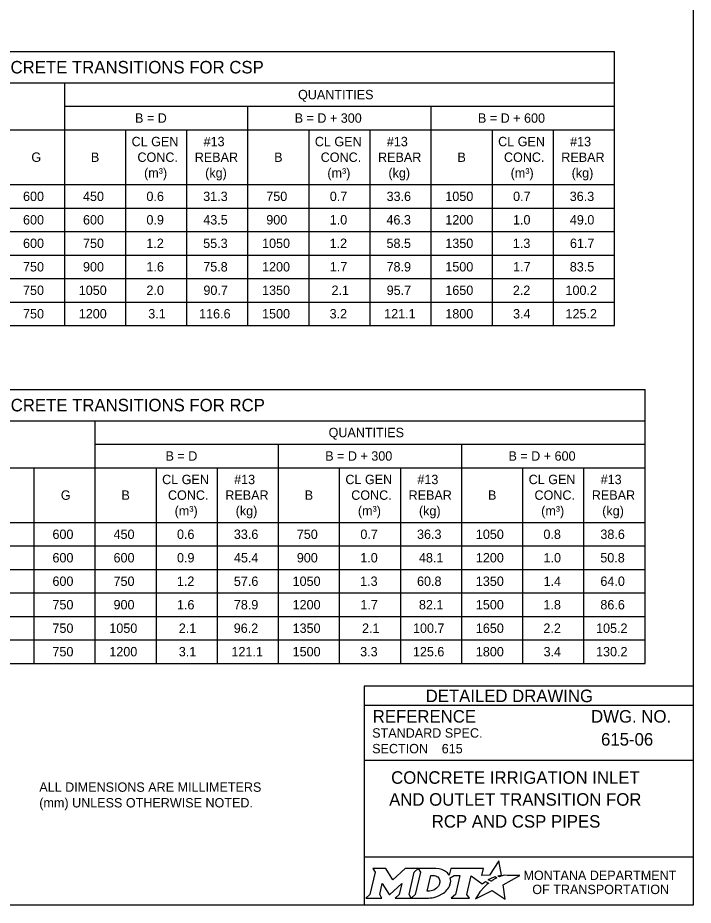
# Model space of a CAD drawing. Extents: x 49991.4 to 50043, y 49987.6 to 50011.4.
# Drawn here: x 50012.44 to 50016.75, y 49987.8 to 49993.47 of the extents above; entities that cross this region are included whole.
import ezdxf

# ---------------------------------------------------------------- set-up
doc = ezdxf.new("R2010")
doc.units = 0
for name, color, linetype in [('Default', 7, 'Continuous'), ('Level 1', 7, 'Continuous'), ('Level 2', 7, 'Continuous'), ('Level 5', 7, 'Continuous')]:
    doc.layers.add(name, color=color, linetype=linetype)

msp = doc.modelspace()

# ---------------------------------------------------------------- linework, layer by layer
at = {"layer": 'Default'}
for points in [[(50015.5126, 49987.9811), (50015.5023, 49987.9867), (50015.5139, 49987.9895), (50015.5255, 49987.9915), (50015.5081, 49988.0816), (50015.4486, 49987.9903), (50015.4013, 49987.9896), (50015.4116, 49988.0337), (50015.2024, 49988.0338), (50015.1923, 49987.9913), (50015.1865, 49987.9996)], [(50014.7056, 49988.0338), (50014.7197, 49988.0104), (50014.6862, 49987.8671), (50014.6605, 49987.8446), (50014.7621, 49987.8446), (50014.7486, 49987.8674), (50014.7648, 49987.9375), (50014.8085, 49987.8685), (50014.8138, 49987.8685), (50014.8889, 49987.938), (50014.8725, 49987.8669), (50014.8478, 49987.8449), (50014.9494, 49987.8449), (50014.9356, 49987.8682), (50014.9688, 49988.0106)], [(50014.9688, 49988.0106), (50014.9941, 49988.0338), (50014.9117, 49988.0338), (50014.8321, 49987.9608), (50014.7876, 49988.0335), (50014.7056, 49988.0338)], [(50015.1077, 49988.0338), (50014.9941, 49988.0338), (50015.0088, 49988.0109), (50014.9749, 49987.8671), (50014.9494, 49987.8449), (50015.06, 49987.8449)], [(50015.1317, 49987.9471), (50015.1305, 49987.939), (50015.1273, 49987.9297), (50015.1231, 49987.9215), (50015.1175, 49987.914), (50015.111, 49987.9071), (50015.1031, 49987.9008), (50015.0948, 49987.8961), (50015.0857, 49987.8922), (50015.0766, 49987.8899), (50015.0674, 49987.889), (50015.0515, 49987.889), (50015.0751, 49987.989), (50015.0911, 49987.989), (50015.0987, 49987.9884), (50015.1063, 49987.9865), (50015.1129, 49987.9835), (50015.119, 49987.9793), (50015.1238, 49987.9743), (50015.1275, 49987.9683), (50015.1302, 49987.9621), (50015.1318, 49987.9547), (50015.1318, 49987.9517), (50015.1317, 49987.9471)], [(50015.3882, 49987.8843), (50015.3729, 49987.8599), (50015.3682, 49987.8524), (50015.3624, 49987.8438), (50015.3601, 49987.8395), (50015.4654, 49987.8926), (50015.5493, 49987.8375), (50015.5362, 49987.9302), (50015.6431, 49987.9886), (50015.5938, 49987.9894), (50015.5637, 49987.9898), (50015.5429, 49987.9901), (50015.5361, 49987.9886), (50015.5312, 49987.9874), (50015.5228, 49987.9851), (50015.5126, 49987.9811)], [(50015.1991, 49987.9747), (50015.2237, 49987.9878), (50015.2606, 49987.9878), (50015.232, 49987.8673), (50015.2045, 49987.8446), (50015.3207, 49987.8446), (50015.3037, 49987.8675), (50015.3319, 49987.9877), (50015.4032, 49987.936), (50015.4243, 49987.9511), (50015.444, 49987.9402)], [(50015.4622, 49987.9535), (50015.4598, 49987.9518), (50015.4415, 49987.9614), (50015.4518, 49987.9671), (50015.4559, 49987.9693), (50015.4645, 49987.9733), (50015.4702, 49987.9759), (50015.4781, 49987.9789), (50015.4854, 49987.9816), (50015.4972, 49987.9742), (50015.4932, 49987.9721), (50015.4886, 49987.9696), (50015.4844, 49987.9674), (50015.4794, 49987.9645), (50015.4775, 49987.9634), (50015.4748, 49987.9618), (50015.4723, 49987.9604), (50015.47, 49987.9588), (50015.4674, 49987.957), (50015.4647, 49987.9552), (50015.4622, 49987.9535)], [(50015.4021, 49987.9004), (50015.4021, 49987.9004)], [(50015.1057, 49987.8522), (50015.1141, 49987.8548), (50015.1271, 49987.8602), (50015.1475, 49987.8712)]]:
    msp.add_lwpolyline(points, dxfattribs=at)
for centre, radius, start, end in [((50015.1308, 49987.9554), 0.0709, 339.5329, 15.8582), ((50015.0868, 49987.9727), 0.1183, 300.9103, 339.1383)]:
    msp.add_arc(centre, radius, start, end, dxfattribs=at)
for centre, major_axis, ratio, start_param, end_param in [((50015.1056, 49987.9864), (0.0834, -0.0037), 0.568097, 0.61298, 1.570796), ((50015.1612, 49987.9937), (0.0361, -0.0295), 0.469099, 1.225588, 1.570796), ((50015.4329, 49987.9305), (-0.0112, -0.0097), 0.021651, 3.157348, 6.283185), ((50015.3952, 49987.8923), (-0.00694, -0.00806), 0.008222, 0, 3.137361), ((50015.4119, 49987.9106), (-0.0098, -0.0102), 0.016458, 3.141593, 6.279097), ((50015.0603, 49987.9932), (0, 0.1484), 0.987302, 3.139398, 3.456847)]:
    msp.add_ellipse(centre, major_axis=major_axis, ratio=ratio, start_param=start_param, end_param=end_param, dxfattribs=at)
at = {"layer": 'Level 1'}
msp.add_lwpolyline([(49999.3835, 49998.9992), (50016.7501, 49998.9992), (50016.7501, 49987.7988), (49999.3835, 49987.7988)], close=True, dxfattribs=at)
at = {"layer": 'Level 2'}
for p, q in [((50008.8375, 49993.2523), (50016.2475, 49993.2523)), ((50008.8375, 49993.0523), (50016.2475, 49993.0523)), ((50012.7375, 49992.9023), (50016.2475, 49992.9023)), ((50008.8375, 49992.7523), (50016.2475, 49992.7523)), ((50008.8375, 49992.4023), (50016.2475, 49992.4023)), ((50008.8375, 49992.2523), (50016.2475, 49992.2523)), ((50008.8375, 49992.1023), (50016.2475, 49992.1023)), ((50008.8375, 49991.9523), (50016.2475, 49991.9523)), ((50008.8375, 49991.8023), (50016.2475, 49991.8023)), ((50008.8375, 49991.6523), (50016.2475, 49991.6523)), ((50008.8375, 49991.5023), (50016.2475, 49991.5023))]:
    msp.add_line(p, q, dxfattribs=at)
for points in [[(50016.2475, 49991.5023), (50016.2475, 49993.2523)], [(50012.7375, 49991.5023), (50012.7375, 49993.0523)], [(50013.9075, 49991.5023), (50013.9075, 49992.9023)], [(50015.0775, 49991.5023), (50015.0775, 49992.9023)], [(50013.1275, 49991.5023), (50013.1275, 49992.7523)], [(50013.5175, 49991.5023), (50013.5175, 49992.7523)], [(50014.2975, 49991.5023), (50014.2975, 49992.7523)], [(50014.6875, 49991.5023), (50014.6875, 49992.7523)], [(50015.4675, 49991.5023), (50015.4675, 49992.7523)], [(50015.8575, 49991.5023), (50015.8575, 49992.7523)], [(50008.6425, 49991.0937), (50016.4425, 49991.0937)], [(50016.4425, 49989.3437), (50016.4425, 49991.0937)], [(50008.6425, 49990.8937), (50016.4425, 49990.8937)], [(50012.9325, 49989.3437), (50012.9325, 49990.8937)], [(50012.9325, 49990.7437), (50016.4425, 49990.7437)], [(50014.1025, 49989.3437), (50014.1025, 49990.7437)], [(50015.2725, 49989.3437), (50015.2725, 49990.7437)], [(50008.6425, 49990.5937), (50016.4425, 49990.5937)], [(50012.5425, 49989.3437), (50012.5425, 49990.5937)], [(50013.3225, 49989.3437), (50013.3225, 49990.5937)], [(50013.7125, 49989.3437), (50013.7125, 49990.5937)], [(50014.4925, 49989.3437), (50014.4925, 49990.5937)], [(50014.8825, 49989.3437), (50014.8825, 49990.5937)], [(50015.6625, 49989.3437), (50015.6625, 49990.5937)], [(50016.0525, 49989.3437), (50016.0525, 49990.5937)], [(50008.6425, 49990.2437), (50016.4425, 49990.2437)], [(50008.6425, 49990.0937), (50016.4425, 49990.0937)], [(50008.6425, 49989.9437), (50016.4425, 49989.9437)], [(50008.6425, 49989.7937), (50016.4425, 49989.7937)], [(50008.6425, 49989.6437), (50016.4425, 49989.6437)], [(50008.6425, 49989.4937), (50016.4425, 49989.4937)], [(50008.6425, 49989.3437), (50016.4425, 49989.3437)]]:
    msp.add_lwpolyline(points, dxfattribs=at)
at = {"layer": 'Level 5'}
for p, q in [((50016.7501, 49989.1988), (50014.6501, 49989.1988)), ((50014.6501, 49989.1988), (50014.6501, 49987.7988)), ((50016.7501, 49989.0738), (50014.6501, 49989.0738)), ((50016.3862, 49988.8587), (50016.3862, 49988.8587)), ((50015.1444, 49988.7993), (50015.1444, 49988.7993)), ((50016.7501, 49988.7238), (50014.6501, 49988.7238)), ((50015.7001, 49988.4747), (50015.7001, 49988.4747)), ((50016.7501, 49988.1057), (50014.6501, 49988.1057))]:
    msp.add_line(p, q, dxfattribs=at)

# ---------------------------------------------------------------- texts
at = {"layer": 'Default'}
for s, p in [('MONTANA DEPARTMENT', (50015.6663, 49987.96)), ('OF TRANSPORTATION', (50015.7225, 49987.87))]:
    msp.add_text(s, height=0.06, dxfattribs=at).set_placement(p)
at = {"layer": 'Level 2'}
for s, height, p in [('METRIC INLET AND OUTLET CONCRETE TRANSITIONS FOR CSP', 0.08, (50010.6738, 49993.1123)), ('QUANTITIES', 0.06, (50014.2272, 49992.9473)), ('B = D', 0.06, (50013.1863, 49992.7973)), ('B = D + 300', 0.06, (50014.2056, 49992.7973)), ('B = D + 600', 0.06, (50015.3756, 49992.7973)), ('CL GEN', 0.06, (50013.1644, 49992.6473)), ('#13', 0.06, (50013.6241, 49992.6473)), ('CL GEN', 0.06, (50014.3344, 49992.6473)), ('#13', 0.06, (50014.7941, 49992.6473)), ('CL GEN', 0.06, (50015.5044, 49992.6473)), ('#13', 0.06, (50015.9641, 49992.6473)), ('G', 0.06, (50012.5248, 49992.5473)), ('B', 0.06, (50012.9048, 49992.5473)), ('CONC.', 0.06, (50013.2017, 49992.5473)), ('REBAR', 0.06, (50013.5677, 49992.5473)), ('B', 0.06, (50014.0748, 49992.5473)), ('CONC.', 0.06, (50014.3717, 49992.5473)), ('REBAR', 0.06, (50014.7377, 49992.5473)), ('B', 0.06, (50015.2448, 49992.5473)), ('CONC.', 0.06, (50015.5417, 49992.5473)), ('REBAR', 0.06, (50015.9077, 49992.5473)), ('(m³)', 0.06, (50013.2443, 49992.4473)), ('(kg)', 0.06, (50013.6341, 49992.4473)), ('(m³)', 0.06, (50014.4143, 49992.4473)), ('(kg)', 0.06, (50014.8041, 49992.4473)), ('(m³)', 0.06, (50015.5843, 49992.4473)), ('(kg)', 0.06, (50015.9741, 49992.4473)), ('600', 0.06, (50012.4714, 49992.2973)), ('450', 0.06, (50012.8543, 49992.2973)), ('0.6', 0.06, (50013.2593, 49992.2973)), ('31.3', 0.06, (50013.6216, 49992.2973)), ('750', 0.06, (50014.0243, 49992.2973)), ('0.7', 0.06, (50014.43, 49992.2973)), ('33.6', 0.06, (50014.7923, 49992.2973)), ('1050', 0.06, (50015.1674, 49992.2973)), ('0.7', 0.06, (50015.6, 49992.2973)), ('36.3', 0.06, (50015.9616, 49992.2973)), ('600', 0.06, (50012.4714, 49992.1473)), ('600', 0.06, (50012.8543, 49992.1473)), ('0.9', 0.06, (50013.2593, 49992.1473)), ('43.5', 0.06, (50013.6219, 49992.1473)), ('900', 0.06, (50014.0243, 49992.1473)), ('1.0', 0.06, (50014.4294, 49992.1473)), ('46.3', 0.06, (50014.7916, 49992.1473)), ('1200', 0.06, (50015.1674, 49992.1473)), ('1.0', 0.06, (50015.5994, 49992.1473)), ('49.0', 0.06, (50015.9625, 49992.1473)), ('600', 0.06, (50012.4714, 49991.9973)), ('750', 0.06, (50012.8543, 49991.9973)), ('1.2', 0.06, (50013.2586, 49991.9973)), ('55.3', 0.06, (50013.6216, 49991.9973)), ('1050', 0.06, (50013.9974, 49991.9973)), ('1.2', 0.06, (50014.4286, 49991.9973)), ('58.5', 0.06, (50014.7919, 49991.9973)), ('1350', 0.06, (50015.1674, 49991.9973)), ('1.3', 0.06, (50015.5986, 49991.9973)), ('61.7', 0.06, (50015.963, 49991.9973)), ('750', 0.06, (50012.4714, 49991.8473)), ('900', 0.06, (50012.8543, 49991.8473)), ('1.6', 0.06, (50013.2593, 49991.8473)), ('75.8', 0.06, (50013.6218, 49991.8473)), ('1200', 0.06, (50013.9974, 49991.8473)), ('1.7', 0.06, (50014.43, 49991.8473)), ('78.9', 0.06, (50014.7923, 49991.8473)), ('1500', 0.06, (50015.1674, 49991.8473)), ('1.7', 0.06, (50015.6, 49991.8473)), ('83.5', 0.06, (50015.9619, 49991.8473)), ('750', 0.06, (50012.4714, 49991.6973)), ('1050', 0.06, (50012.8274, 49991.6973)), ('2.0', 0.06, (50013.2594, 49991.6973)), ('90.7', 0.06, (50013.623, 49991.6973)), ('1350', 0.06, (50013.9974, 49991.6973)), ('2.1', 0.06, (50014.4408, 49991.6973)), ('95.7', 0.06, (50014.793, 49991.6973)), ('1650', 0.06, (50015.1674, 49991.6973)), ('2.2', 0.06, (50015.5986, 49991.6973)), ('100.2', 0.06, (50015.9347, 49991.6973)), ('750', 0.06, (50012.4714, 49991.5473)), ('1200', 0.06, (50012.8274, 49991.5473)), ('3.1', 0.06, (50013.2708, 49991.5473)), ('116.6', 0.06, (50013.5954, 49991.5473)), ('1500', 0.06, (50013.9974, 49991.5473)), ('3.2', 0.06, (50014.4286, 49991.5473)), ('121.1', 0.06, (50014.7769, 49991.5473)), ('1800', 0.06, (50015.1674, 49991.5473)), ('3.4', 0.06, (50015.5998, 49991.5473)), ('125.2', 0.06, (50015.9347, 49991.5473)), ('METRIC INLET AND OUTLET CONCRETE TRANSITIONS FOR RCP', 0.08, (50010.6749, 49990.9537)), ('QUANTITIES', 0.06, (50014.4222, 49990.7887)), ('B = D', 0.06, (50013.3813, 49990.6387)), ('B = D + 300', 0.06, (50014.4006, 49990.6387)), ('B = D + 600', 0.06, (50015.5706, 49990.6387)), ('CL GEN', 0.06, (50013.3594, 49990.4887)), ('#13', 0.06, (50013.8191, 49990.4887)), ('CL GEN', 0.06, (50014.5294, 49990.4887)), ('#13', 0.06, (50014.9891, 49990.4887)), ('CL GEN', 0.06, (50015.6994, 49990.4887)), ('#13', 0.06, (50016.1591, 49990.4887)), ('G', 0.06, (50012.7127, 49990.3887)), ('B', 0.06, (50013.0998, 49990.3887)), ('CONC.', 0.06, (50013.3967, 49990.3887)), ('REBAR', 0.06, (50013.7627, 49990.3887)), ('B', 0.06, (50014.2698, 49990.3887)), ('CONC.', 0.06, (50014.5667, 49990.3887)), ('REBAR', 0.06, (50014.9327, 49990.3887)), ('B', 0.06, (50015.4398, 49990.3887)), ('CONC.', 0.06, (50015.7367, 49990.3887)), ('REBAR', 0.06, (50016.1027, 49990.3887)), ('(m³)', 0.06, (50013.4393, 49990.2887)), ('(kg)', 0.06, (50013.8291, 49990.2887)), ('(m³)', 0.06, (50014.6093, 49990.2887)), ('(kg)', 0.06, (50014.9991, 49990.2887)), ('(m³)', 0.06, (50015.7793, 49990.2887)), ('(kg)', 0.06, (50016.1691, 49990.2887)), ('600', 0.06, (50012.6593, 49990.1387)), ('450', 0.06, (50013.0493, 49990.1387)), ('0.6', 0.06, (50013.4543, 49990.1387)), ('33.6', 0.06, (50013.8173, 49990.1387)), ('750', 0.06, (50014.2193, 49990.1387)), ('0.7', 0.06, (50014.625, 49990.1387)), ('36.3', 0.06, (50014.9866, 49990.1387)), ('1050', 0.06, (50015.3624, 49990.1387)), ('0.8', 0.06, (50015.7938, 49990.1387)), ('38.6', 0.06, (50016.1573, 49990.1387)), ('600', 0.06, (50012.6593, 49989.9887)), ('600', 0.06, (50013.0493, 49989.9887)), ('0.9', 0.06, (50013.4543, 49989.9887)), ('45.4', 0.06, (50013.8178, 49989.9887)), ('900', 0.06, (50014.2193, 49989.9887)), ('1.0', 0.06, (50014.6244, 49989.9887)), ('48.1', 0.06, (50014.9989, 49989.9887)), ('1200', 0.06, (50015.3624, 49989.9887)), ('1.0', 0.06, (50015.7944, 49989.9887)), ('50.8', 0.06, (50016.1568, 49989.9887)), ('600', 0.06, (50012.6593, 49989.8387)), ('750', 0.06, (50013.0493, 49989.8387)), ('1.2', 0.06, (50013.4536, 49989.8387)), ('57.6', 0.06, (50013.8173, 49989.8387)), ('1050', 0.06, (50014.1924, 49989.8387)), ('1.3', 0.06, (50014.6236, 49989.8387)), ('60.8', 0.06, (50014.9868, 49989.8387)), ('1350', 0.06, (50015.3624, 49989.8387)), ('1.4', 0.06, (50015.7948, 49989.8387)), ('64.0', 0.06, (50016.1575, 49989.8387)), ('750', 0.06, (50012.6593, 49989.6887)), ('900', 0.06, (50013.0493, 49989.6887)), ('1.6', 0.06, (50013.4543, 49989.6887)), ('78.9', 0.06, (50013.8173, 49989.6887)), ('1200', 0.06, (50014.1924, 49989.6887)), ('1.7', 0.06, (50014.625, 49989.6887)), ('82.1', 0.06, (50014.9989, 49989.6887)), ('1500', 0.06, (50015.3624, 49989.6887)), ('1.8', 0.06, (50015.7938, 49989.6887)), ('86.6', 0.06, (50016.1573, 49989.6887)), ('750', 0.06, (50012.6593, 49989.5387)), ('1050', 0.06, (50013.0224, 49989.5387)), ('2.1', 0.06, (50013.4658, 49989.5387)), ('96.2', 0.06, (50013.8167, 49989.5387)), ('1350', 0.06, (50014.1924, 49989.5387)), ('2.1', 0.06, (50014.6358, 49989.5387)), ('100.7', 0.06, (50014.9611, 49989.5387)), ('1650', 0.06, (50015.3624, 49989.5387)), ('2.2', 0.06, (50015.7936, 49989.5387)), ('105.2', 0.06, (50016.1297, 49989.5387)), ('750', 0.06, (50012.6593, 49989.3887)), ('1200', 0.06, (50013.0224, 49989.3887)), ('3.1', 0.06, (50013.4658, 49989.3887)), ('121.1', 0.06, (50013.8019, 49989.3887)), ('1500', 0.06, (50014.1924, 49989.3887)), ('3.3', 0.06, (50014.6236, 49989.3887)), ('125.6', 0.06, (50014.9604, 49989.3887)), ('1800', 0.06, (50015.3624, 49989.3887)), ('3.4', 0.06, (50015.7948, 49989.3887)), ('130.2', 0.06, (50016.1297, 49989.3887)), ('615-06', 0.08, (50016.1614, 49988.8187)), ('615', 0.06, (50015.1444, 49988.7693)), ('CONCRETE IRRIGATION INLET', 0.08, (50014.8214, 49988.5747)), ('ALL DIMENSIONS ARE MILLIMETERS', 0.06, (50012.5752, 49988.5236)), ('AND OUTLET TRANSITION FOR', 0.08, (50014.8087, 49988.4347)), ('(mm) UNLESS OTHERWISE NOTED.', 0.06, (50012.5752, 49988.4236)), ('RCP AND CSP PIPES', 0.08, (50015.0809, 49988.2947))]:
    msp.add_text(s, height=height, dxfattribs=at).set_placement(p)
at = {"layer": 'Level 5'}
for s, height, p in [('DETAILED DRAWING', 0.0799, (50015.0418, 49989.0963)), ('REFERENCE', 0.08, (50014.7037, 49988.9654)), ('DWG. NO.', 0.08, (50016.0979, 49988.9654)), ('STANDARD SPEC.', 0.06, (50014.7004, 49988.8694)), ('SECTION', 0.06, (50014.7004, 49988.7694))]:
    msp.add_text(s, height=height, dxfattribs=at).set_placement(p)

doc.saveas('drawing.dxf')
